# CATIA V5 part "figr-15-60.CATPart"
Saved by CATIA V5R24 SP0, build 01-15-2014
Part number: Part1
Bounding box of the stored display mesh (mm): x -35.944 to 35.944, y -33.497 to 33.497, z 0 to 50.428
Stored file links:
  D:\KAVITA\CATIA V5-6R2014 Project_ Kavita\CATIA V5-6R2014_partfiles\Partfiles\c15_catia_v5-6r2014_prt\figr-15-60.CATPart
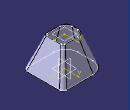
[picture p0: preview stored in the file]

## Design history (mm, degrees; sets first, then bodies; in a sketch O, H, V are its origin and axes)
SheetMetalParameters1: Thickness 1, BendRadius 2, KFactor 0.400515 {= log(min(100,max(20*SheetMetalParameters1.BendRadius,SheetMetalParameters1.Thickness)/SheetMetalParameters1.Thickness))/log(100)/2}, ReliefRadialLength 1, ReliefAxialLength 2, MinimumBendRadius 0
Body1 (main body)
  Sketch1 on xy-plane, origin (0, 0, 0), H (1, 0, 0), V (0, 1, 0)
    line L1 (-15, -32.5532) -> (30, -32.5532)
    line L2 (35, -27.5532) -> (35, 27.5532)
    line L3 (30, 32.5532) -> (-15, 32.5532)
    line L4 (-35, 12.5532) -> (-35, -12.5532)
    arc A1 centre (-15, -12.5532) radius 20 from (-35, -12.5532) to (-15, -32.5532) ccw
    arc A2 centre (-15, 12.5532) radius 20 from (-35, 12.5532) to (-15, 32.5532) cw
    arc A3 centre (30, -27.5532) radius 5 from (30, -32.5532) to (35, -27.5532) ccw
    arc A4 centre (30, 27.5532) radius 5 from (35, 27.5532) to (30, 32.5532) ccw
    radius A1 = 20
    radius A2 = 20
    radius A3 = 5
    radius A4 = 5
    distance L2 L4 = 70
    horizontal: L1 H, L3 H
    vertical: L2 V, L4 V
    tangency: A1 L4, A1 L1, A2 L4, A2 L3, A3 L1, A3 L2, A4 L2, A4 L3
    symmetry: L3 L1 H, L4 L2 V
  Plane1: type Offset, RefPlane xy-plane, Offset 50
  Sketch2 "Sketch.2" on Plane1, origin (0, 0, 50), H (1, 0, 0), V (0, 1, 0)
    line L1 (-7.5, 15) -> (14.5, 15)
    line L2 (17.5, 12) -> (17.5, -12)
    line L3 (14.5, -15) -> (-7.5, -15)
    line L4 (-17.5, -5) -> (-17.5, 5)
    arc A1 centre (-7.5, -5) radius 10 from (-7.5, -15) to (-17.5, -5) cw
    arc A2 centre (-7.5, 5) radius 10 from (-17.5, 5) to (-7.5, 15) cw
    arc A3 centre (14.5, 12) radius 3 from (14.5, 15) to (17.5, 12) cw
    arc A4 centre (14.5, -12) radius 3 from (17.5, -12) to (14.5, -15) cw
    radius A1 = 10
    radius A2 = 10
    radius A3 = 3
    radius A4 = 3
    distance L4 L2 = 35
    distance L1 L3 = 30
    horizontal: L1 H, L3 H
    vertical: L2 V, L4 V
    tangency: A1 L3, A1 L4, A2 L4, A2 L1, A3 L1, A3 L2, A4 L2, A4 L3
    symmetry: L4 L2 V, L1 L3 H
  Hopper1: KFacteur 0.400515 {= SheetMetalParameters1.KFactor}, HopperFixedSideType 0, HopperType 0, Hopper_InvariantPoint vertex [element of Sketch1 | element of Sketch1], Hopper_NeutralFiber 0, Hopper_ReferenceEdge edge [face of Hopper1 | face of Hopper1], Hopper_Surface {loft Sections (Sketch1; Sketch2), SectionCouplingPoints ({coupling CouplingPoints (vertex [element of Sketch1 | element of Sketch1]; vertex [element of Sketch2 | element of Sketch2])}; {coupling CouplingPoints (vertex [element of Sketch1 | element of Sketch1]; vertex [element of Sketch2 | element of Sketch2])}; {coupling CouplingPoints (vertex [element of Sketch1 | element of Sketch1]; vertex [element of Sketch2 | element of Sketch2])}; {coupling CouplingPoints (vertex [element of Sketch1 | element of Sketch1]; vertex [element of Sketch2 | element of Sketch2])}; {coupling CouplingPoints (vertex [element of Sketch1 | element of Sketch1]; vertex [element of Sketch2 | element of Sketch2])}; {coupling CouplingPoints (vertex [element of Sketch1 | element of Sketch1]; vertex [element of Sketch2 | element of Sketch2])}; {coupling CouplingPoints (vertex [element of Sketch1 | element of Sketch1]; vertex [element of Sketch2 | element of Sketch2])}; {coupling CouplingPoints (vertex [element of Sketch1 | element of Sketch1]; vertex [element of Sketch2 | element of Sketch2])})}, Hopper_TearWires edge [face of Hopper1 | face of Hopper1], Hopper_Thickness 1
